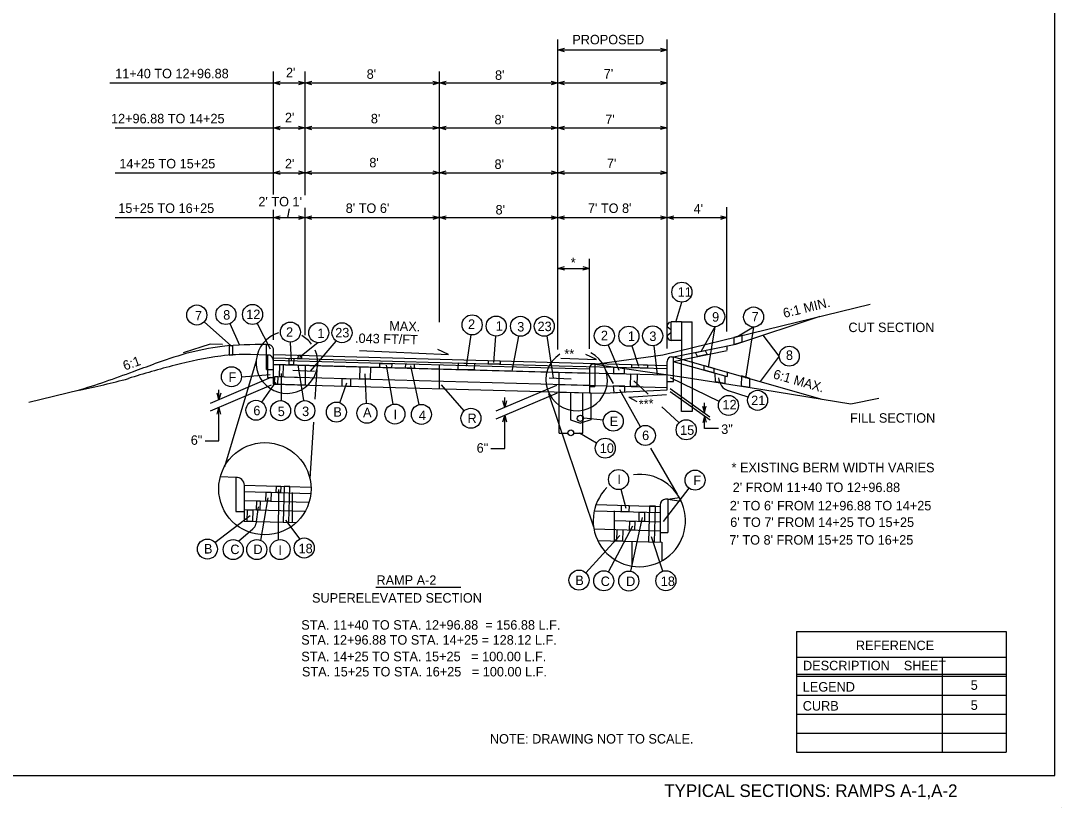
# Model space of a CAD drawing. Extents: x -210 to 558, y -150 to 205.
# Drawn here: x 491.9 to 557.8, y -150.3 to -100.6 of the extents above; entities that cross this region are included whole.
import ezdxf

# ---------------------------------------------------------------- set-up
doc = ezdxf.new("R2010")
doc.units = 0
for name, color, linetype in [('Level 1', 7, 'Continuous'), ('Level 4', 7, 'Continuous'), ('Level 6', 7, 'Continuous'), ('Level 60', 7, 'Continuous'), ('Level 7', 7, 'Continuous')]:
    doc.layers.add(name, color=color, linetype=linetype)

msp = doc.modelspace()

# ---------------------------------------------------------------- linework, layer by layer
at = {"layer": 'Level 1'}
for p, q in [((557.356, -148.31), (557.356, -64.342)), ((423.408, -148.31), (557.356, -148.31)), ((557.752, -150.31), (557.752, -150.31))]:
    msp.add_line(p, q, dxfattribs=at)
at = {"layer": 'Level 4'}
for p, q in [((525.911, -121.363), (525.911, -101.746)), ((532.821, -121.29), (532.821, -101.746)), ((525.911, -102.398), (532.821, -102.398)), ((507.923, -111.546), (507.923, -103.773)), ((509.923, -111.584), (509.923, -103.773)), ((518.423, -119.63), (518.423, -103.773)), ((497.577, -104.491), (507.923, -104.491)), ((507.923, -104.491), (509.923, -104.491)), ((509.923, -104.491), (518.423, -104.491)), ((518.276, -104.473), (518.693, -104.473)), ((518.423, -104.491), (525.911, -104.491)), ((525.911, -104.491), (532.821, -104.491)), ((497.908, -107.33), (507.923, -107.33)), ((507.923, -107.33), (509.923, -107.33)), ((509.923, -107.33), (518.423, -107.33)), ((518.276, -107.312), (518.693, -107.312)), ((518.423, -107.33), (525.911, -107.33)), ((525.911, -107.33), (532.821, -107.33)), ((497.908, -110.169), (507.923, -110.169)), ((507.923, -110.169), (509.923, -110.169)), ((509.923, -110.169), (518.423, -110.169)), ((518.276, -110.151), (518.693, -110.151)), ((518.423, -110.169), (525.911, -110.169)), ((525.911, -110.169), (532.821, -110.169)), ((507.923, -120.735), (507.923, -112.51)), ((508.912, -112.453), (508.798, -113.001)), ((509.923, -120.44), (509.923, -112.397)), ((536.611, -120.213), (536.611, -112.346)), ((497.908, -113.008), (507.923, -113.008)), ((507.923, -113.008), (509.923, -113.008)), ((509.923, -113.008), (518.423, -113.008)), ((518.276, -112.99), (518.693, -112.99)), ((518.423, -113.008), (525.911, -113.008)), ((525.911, -113.008), (536.611, -113.008)), ((527.911, -121.316), (527.911, -115.619)), ((525.911, -116.22), (527.911, -116.22)), ((533.38, -119.615), (533.756, -118.36)), ((503.543, -119.594), (505.267, -121.133)), ((505.167, -119.717), (505.768, -121.079)), ((506.884, -119.701), (507.71, -121.316)), ((520.398, -120.424), (520.111, -122.414)), ((535.832, -119.909), (534.965, -121.502)), ((535.832, -119.909), (535.428, -122.484)), ((538.293, -119.933), (537.346, -120.519)), ((538.293, -119.933), (537.789, -123.165)), ((539.917, -121.772), (538.906, -120.441)), ((503.923, -121.023), (502.211, -121.572)), ((504.706, -121.027), (503.923, -121.023)), ((508.985, -120.91), (509.046, -122.075)), ((510.718, -120.925), (509.59, -121.834)), ((510.265, -122.721), (511.894, -120.816)), ((521.966, -120.5), (521.848, -122.181)), ((523.429, -120.508), (522.995, -122.719)), ((525.222, -120.496), (525.607, -123.165)), ((529.096, -121.073), (529.761, -122.67)), ((513.359, -121.418), (518.984, -121.67)), ((518.984, -121.67), (518.319, -121.35)), ((528.349, -121.984), (527.684, -121.664)), ((530.596, -121.115), (531.011, -122.416)), ((531.981, -121.117), (532.192, -122.937)), ((509.84, -124.587), (509.486, -122.326)), ((515.498, -124.814), (515.074, -122.347)), ((517.144, -124.839), (516.614, -122.383)), ((526.09, -121.9), (528.349, -121.984)), ((539.917, -121.772), (538.7, -123.375)), ((505.898, -123.078), (507.719, -122.94)), ((508.43, -124.591), (508.424, -122.869)), ((513.803, -124.752), (513.713, -122.884)), ((507.747, -123.13), (503.911, -124.762)), ((507.778, -123.613), (503.911, -125.259)), ((507.194, -124.688), (508.062, -123.413)), ((512.114, -124.717), (512.567, -123.457)), ((519.993, -125.228), (518.548, -123.587)), ((525.829, -123.627), (521.993, -125.259)), ((530.717, -123.336), (531.631, -124.181)), ((536.114, -124.645), (533.037, -123.156)), ((504.465, -124.526), (504.465, -123.896)), ((525.861, -124.11), (521.993, -125.756)), ((531.136, -126.238), (529.837, -123.898)), ((530.398, -124.376), (532.792, -124.206)), ((530.398, -124.376), (530.912, -124.641)), ((533.012, -123.82), (535.534, -125.607)), ((533.013, -124.002), (535.543, -125.794)), ((537.944, -124.367), (536.703, -123.967)), ((504.465, -127.122), (504.465, -125.023)), ((522.547, -125.023), (522.547, -124.394)), ((532.497, -124.98), (533.573, -125.974)), ((535.178, -125.357), (535.178, -124.727)), ((522.547, -127.62), (522.547, -125.52)), ((528.799, -125.825), (527.544, -125.705)), ((535.188, -126.357), (535.188, -125.542)), ((536.064, -126.357), (535.188, -126.357)), ((528.361, -127.278), (527.28, -126.652)), ((503.589, -127.122), (504.465, -127.122)), ((521.671, -127.62), (522.547, -127.62)), ((508.243, -130.21), (508.214, -133.391)), ((529.904, -130.194), (530.209, -131.401)), ((534.201, -130.121), (532.568, -132.235)), ((507.123, -133.433), (507.595, -130.734)), ((506.956, -131.302), (506.814, -132.394)), ((504.22, -133.563), (506.45, -131.861)), ((508.687, -132.145), (509.587, -133.343)), ((530.534, -135.385), (531.266, -131.991)), ((505.714, -133.477), (506.618, -132.705)), ((529.111, -135.425), (530.656, -132.519)), ((527.676, -135.476), (529.822, -133.13)), ((532.546, -135.382), (531.836, -133.211)), ((514.403, -136.386), (519.778, -136.386)), ((541.015, -139.191), (541.015, -146.826)), ((541.015, -139.191), (554.27, -139.191)), ((554.27, -139.191), (554.27, -146.826)), ((541.015, -140.826), (554.27, -140.826)), ((550.224, -140.826), (550.224, -146.826)), ((541.015, -141.901), (554.27, -141.901)), ((541.015, -142.026), (554.27, -142.026)), ((541.015, -143.226), (554.27, -143.226)), ((541.015, -144.426), (554.27, -144.426)), ((541.015, -145.626), (554.27, -145.626)), ((541.015, -146.826), (554.27, -146.826))]:
    msp.add_line(p, q, dxfattribs=at)
for points in [[(526.331, -102.514), (525.911, -102.398), (526.331, -102.286)], [(532.401, -102.282), (532.821, -102.398), (532.401, -102.51)], [(508.343, -104.607), (507.923, -104.491), (508.343, -104.379)], [(509.503, -104.375), (509.923, -104.491), (509.503, -104.603)], [(510.343, -104.607), (509.923, -104.491), (510.343, -104.379)], [(518.003, -104.375), (518.423, -104.491), (518.003, -104.603)], [(518.843, -104.607), (518.423, -104.491), (518.843, -104.379)], [(525.491, -104.375), (525.911, -104.491), (525.491, -104.603)], [(526.331, -104.607), (525.911, -104.491), (526.331, -104.379)], [(532.401, -104.375), (532.821, -104.491), (532.401, -104.603)], [(508.343, -107.446), (507.923, -107.33), (508.343, -107.218)], [(509.503, -107.214), (509.923, -107.33), (509.503, -107.442)], [(510.343, -107.446), (509.923, -107.33), (510.343, -107.218)], [(518.003, -107.214), (518.423, -107.33), (518.003, -107.442)], [(518.843, -107.446), (518.423, -107.33), (518.843, -107.218)], [(525.491, -107.214), (525.911, -107.33), (525.491, -107.442)], [(526.331, -107.446), (525.911, -107.33), (526.331, -107.218)], [(532.401, -107.214), (532.821, -107.33), (532.401, -107.442)], [(508.343, -110.285), (507.923, -110.169), (508.343, -110.057)], [(509.503, -110.053), (509.923, -110.169), (509.503, -110.281)], [(510.343, -110.285), (509.923, -110.169), (510.343, -110.057)], [(518.003, -110.053), (518.423, -110.169), (518.003, -110.281)], [(518.843, -110.285), (518.423, -110.169), (518.843, -110.057)], [(525.491, -110.053), (525.911, -110.169), (525.491, -110.281)], [(526.331, -110.285), (525.911, -110.169), (526.331, -110.057)], [(532.401, -110.053), (532.821, -110.169), (532.401, -110.281)], [(508.343, -113.124), (507.923, -113.008), (508.343, -112.896)], [(509.503, -112.892), (509.923, -113.008), (509.503, -113.12)], [(510.343, -113.124), (509.923, -113.008), (510.343, -112.896)], [(518.003, -112.892), (518.423, -113.008), (518.003, -113.12)], [(518.843, -113.124), (518.423, -113.008), (518.843, -112.896)], [(525.491, -112.892), (525.911, -113.008), (525.491, -113.12)], [(526.331, -113.124), (525.911, -113.008), (526.331, -112.896)], [(532.401, -112.892), (532.821, -113.008), (532.401, -113.12)], [(533.241, -113.124), (532.821, -113.008), (533.241, -112.896)], [(536.191, -112.892), (536.611, -113.008), (536.191, -113.12)], [(526.331, -116.336), (525.911, -116.22), (526.331, -116.108)], [(527.491, -116.104), (527.911, -116.22), (527.491, -116.332)], [(504.581, -124.106), (504.465, -124.526), (504.353, -124.106)], [(504.349, -125.443), (504.465, -125.023), (504.577, -125.443)], [(522.663, -124.603), (522.547, -125.023), (522.435, -124.603)], [(535.062, -124.937), (535.178, -125.357), (535.29, -124.937)], [(522.431, -125.94), (522.547, -125.52), (522.659, -125.94)], [(535.304, -125.962), (535.188, -125.542), (535.076, -125.962)]]:
    msp.add_lwpolyline(points, dxfattribs=at)
for points in [[(537.035, -120.601), (537.049, -121.041), (537.577, -120.877), (537.573, -120.451)], [(534.624, -121.533), (535.236, -121.413), (535.366, -121.674), (534.753, -121.794)], [(535.17, -122.367), (535.771, -122.537), (535.768, -122.829), (535.167, -122.659)], [(535.871, -122.855), (536.464, -123.02), (536.474, -123.499), (535.879, -123.406)], [(537.518, -123.021), (537.516, -123.644), (538.055, -123.735), (538.052, -123.185)]]:
    msp.add_lwpolyline(points, close=True, dxfattribs=at)
for centre in [(533.757, -117.726), (503.07, -119.171), (504.911, -119.137), (506.595, -119.137), (535.834, -119.275), (538.295, -119.298), (508.99, -120.251), (510.785, -120.294), (512.255, -120.294), (520.489, -119.796), (522.011, -119.868), (523.551, -119.886), (525.05, -119.886), (528.852, -120.488), (530.404, -120.511), (531.908, -120.488), (540.551, -121.774), (505.264, -123.076), (536.702, -124.891), (538.545, -124.568), (506.815, -125.196), (508.369, -125.222), (509.905, -125.222), (511.899, -125.314), (513.833, -125.385), (515.606, -125.439), (517.278, -125.459), (520.412, -125.704), (529.419, -125.884), (531.444, -126.792), (534.029, -126.434), (528.91, -127.595), (529.749, -129.579), (534.589, -129.619), (503.741, -133.977), (505.375, -134.013), (506.866, -134.013), (508.34, -134.013), (509.866, -133.912), (527.248, -135.944), (528.813, -135.985), (530.4, -136.005), (532.743, -135.984)]:
    msp.add_circle(centre, 0.634, dxfattribs=at)
for centre, radius, start, end in [((537.033, -123.058), 0.967, 184.63452, 250.04639), ((506.33, -132.307), 0.491, 305.90709, 349.76504)]:
    msp.add_arc(centre, radius, start, end, dxfattribs=at)
at = {"layer": 'Level 6'}
for p, q in [((532.553, -121.696), (545.664, -118.477)), ((507.547, -121.702), (506.459, -121.669)), ((507.547, -121.702), (507.547, -123.134)), ((528.244, -122.283), (532.553, -121.696)), ((507.902, -122.021), (507.902, -123.548)), ((507.902, -122.036), (527.911, -122.586)), ((507.902, -122.3), (527.911, -122.85)), ((518.423, -123.838), (518.423, -122.325)), ((528.244, -122.283), (528.143, -122.283)), ((528.244, -122.283), (528.244, -123.692)), ((528.244, -122.283), (533.764, -123.072)), ((507.902, -123.062), (527.911, -123.613)), ((527.911, -122.532), (527.911, -124.099)), ((533.764, -123.072), (538.88, -123.878)), ((507.547, -123.134), (507.902, -123.134)), ((507.902, -123.548), (527.99, -124.101)), ((527.911, -123.692), (528.244, -123.692)), ((495.64, -123.927), (492.454, -124.7)), ((526.717, -124.066), (526.717, -125.796)), ((527.99, -124.101), (527.99, -125.796)), ((538.88, -123.878), (544.439, -124.792)), ((544.439, -124.792), (546.219, -124.423)), ((526.717, -125.8), (527.353, -126.01)), ((527.99, -125.8), (527.353, -126.01)), ((505.538, -129.443), (504.554, -129.414)), ((505.538, -129.443), (505.538, -131.592)), ((506.071, -129.922), (506.071, -132.213)), ((506.071, -129.945), (510.297, -130.061)), ((506.071, -130.341), (510.284, -130.457)), ((506.107, -130.907), (510.171, -131.019)), ((509.103, -130.396), (509.103, -132.297)), ((532.875, -130.824), (532.724, -130.824)), ((532.875, -130.824), (533.605, -130.724)), ((532.875, -130.824), (532.875, -132.939)), ((532.875, -130.824), (533.705, -130.942)), ((505.538, -131.592), (506.071, -131.592)), ((506.071, -131.485), (509.926, -131.591)), ((528.183, -131.56), (532.375, -131.676)), ((528.326, -131.168), (532.375, -131.279)), ((529.486, -133.468), (529.486, -131.567)), ((532.375, -131.198), (532.375, -133.548)), ((506.071, -132.213), (509.365, -132.304)), ((529.486, -132.182), (532.375, -132.262)), ((528.192, -132.704), (532.375, -132.819)), ((532.375, -132.939), (532.875, -132.939)), ((528.441, -133.44), (532.494, -133.551)), ((530.584, -133.499), (530.584, -135.053)), ((532.494, -133.551), (532.494, -134.719))]:
    msp.add_line(p, q, dxfattribs=at)
msp.add_circle((527.337, -125.709), 0.196, dxfattribs=at)
for centre, radius, start, end in [((506.143, -133.468), 11.803, 88.4676, 97.57992), ((507.569, -122.043), 0.342, 1.12623, 93.69626), ((514.292, -171.853), 51.086, 104.27965, 107.71771), ((507.498, -143.875), 22.298, 97.5041, 105.09419), ((528.153, -122.524), 0.242, 92.27579, 181.84757), ((482.471, -61.462), 63.839, 281.90418, 284.7694), ((505.571, -129.955), 0.513, 1.12623, 93.69626), ((532.738, -131.186), 0.363, 92.27579, 181.84757)]:
    msp.add_arc(centre, radius, start, end, dxfattribs=at)
at = {"layer": 'Level 60'}
for points in [[(505.347, -121.112), (505.112, -121.127), (505.112, -121.702), (505.354, -121.687)], [(509.492, -121.922), (509.498, -121.717), (509.694, -121.722), (509.688, -121.928)], [(508.301, -123.073), (508.322, -122.312), (508.533, -122.318), (508.512, -123.079)], [(508.907, -122.308), (508.918, -121.907), (509.207, -121.915), (509.196, -122.316)], [(514.645, -122.494), (514.652, -122.23), (515.398, -122.251), (515.391, -122.515)], [(516.276, -122.52), (516.292, -122.257), (516.829, -122.29), (516.813, -122.553)], [(519.609, -122.622), (519.62, -122.201), (520.631, -122.229), (520.62, -122.65)], [(521.526, -122.253), (521.532, -122.047), (522.262, -122.067), (522.256, -122.273)], [(530.589, -122.502), (530.595, -122.296), (531.586, -122.324), (531.58, -122.529)], [(507.993, -123.551), (508.007, -123.065), (508.188, -123.07), (508.175, -123.556)], [(513.374, -123.222), (513.395, -122.46), (514.055, -122.478), (514.034, -123.24)], [(529.444, -122.873), (529.455, -122.471), (530.115, -122.489), (530.103, -122.891)], [(530.496, -123.684), (530.517, -122.902), (530.926, -122.914), (530.904, -123.695)], [(512.263, -123.677), (512.276, -123.192), (512.803, -123.206), (512.789, -123.692)], [(529.444, -124.085), (530.149, -124.034), (530.15, -123.674), (529.42, -123.654)], [(508.097, -130.397), (508.107, -130.001), (508.381, -130.008), (508.37, -130.404)], [(508.594, -130.014), (508.532, -132.281), (508.887, -132.291), (508.949, -130.024)], [(506.853, -131.506), (506.869, -130.928), (507.076, -130.934), (507.06, -131.512)], [(507.44, -130.944), (507.455, -130.379), (507.778, -130.388), (507.763, -130.953)], [(506.257, -132.218), (506.278, -131.49), (506.624, -131.5), (506.604, -132.228)], [(529.933, -131.608), (529.944, -131.212), (530.422, -131.225), (530.411, -131.622)], [(531.701, -131.261), (531.638, -133.527), (532.032, -133.538), (532.094, -131.271)], [(530.439, -132.766), (530.455, -132.209), (530.774, -132.218), (530.759, -132.775)], [(531.046, -132.225), (531.062, -131.639), (531.398, -131.649), (531.382, -132.234)], [(529.639, -133.473), (529.659, -132.744), (530.02, -132.754), (530, -133.482)]]:
    msp.add_lwpolyline(points, close=True, dxfattribs=at)
at = {"layer": 'Level 7'}
for p, q in [((532.834, -119.829), (532.982, -119.625)), ((532.982, -119.625), (533.069, -119.61)), ((533.736, -119.61), (533.069, -119.61)), ((533.069, -120.776), (533.069, -119.61)), ((533.736, -119.61), (533.736, -121.86)), ((533.736, -119.61), (534.403, -119.61)), ((534.403, -122.112), (534.403, -119.61)), ((537.177, -121.011), (542.499, -119.254)), ((533.039, -120.084), (532.849, -119.937)), ((532.849, -120.449), (533.039, -120.301)), ((507.474, -122.609), (507.474, -121.04)), ((507.474, -121.04), (507.658, -121.04)), ((532.982, -120.761), (532.834, -120.556)), ((532.982, -120.761), (533.069, -120.776)), ((533.736, -120.776), (533.069, -120.776)), ((533.233, -121.812), (537.177, -121.011)), ((507.923, -123.549), (507.923, -121.441)), ((507.923, -121.673), (525.985, -122.17)), ((533.209, -122.103), (536.62, -121.41)), ((536.611, -121.126), (536.611, -121.372)), ((506.831, -122.06), (504.812, -128.771)), ((507.923, -121.879), (525.985, -122.376)), ((507.923, -122.281), (525.943, -122.777)), ((509.923, -122.336), (509.923, -123.604)), ((525.985, -122.17), (532.822, -122.358)), ((525.985, -122.376), (532.822, -122.564)), ((532.822, -123.895), (532.822, -122.105)), ((533.104, -121.812), (533.233, -121.812)), ((533.209, -122.103), (536.62, -123.064)), ((533.233, -123.371), (533.233, -121.812)), ((533.233, -121.812), (542.601, -124.49)), ((533.736, -125.276), (533.736, -121.86)), ((534.403, -122.112), (534.403, -125.276)), ((507.474, -122.609), (507.923, -122.609)), ((507.923, -123.063), (509.923, -123.118)), ((509.143, -122.669), (510.52, -122.733)), ((510.665, -122.645), (510.546, -124.505)), ((525.943, -122.777), (532.822, -122.966)), ((525.985, -124.046), (525.985, -122.778)), ((528.907, -122.64), (529.403, -123.496)), ((536.62, -122.772), (536.62, -123.064)), ((509.923, -123.604), (507.923, -123.549)), ((525.367, -123.154), (526.744, -123.218)), ((525.985, -123.56), (532.822, -123.748)), ((532.822, -123.371), (533.233, -123.371)), ((525.315, -124.13), (528.173, -132.581)), ((525.985, -124.046), (528.877, -124.125)), ((525.985, -126.652), (525.985, -124.046)), ((527.494, -126.652), (527.494, -124.089)), ((528.877, -124.125), (530.222, -124.029)), ((530.222, -124.029), (532.822, -123.895)), ((534.403, -125.276), (533.736, -125.276)), ((510.453, -125.957), (510.226, -129.514)), ((525.985, -126.652), (526.549, -126.652)), ((526.908, -126.652), (527.494, -126.652)), ((531.773, -127.59), (533.462, -130.506))]:
    msp.add_line(p, q, dxfattribs=at)
for centre, radius in [((526.729, -126.625), 0.18), ((507.378, -130.163), 2.92)]:
    msp.add_circle(centre, radius, dxfattribs=at)
for centre, radius, start, end in [((508.774, -122.182), 1.947, 105.71295, 23.99916), ((532.897, -119.875), 0.0781, 144.08393, 232.1285), ((532.991, -120.24), 0.0781, 307.8715, 360), ((507.205, -147.088), 26.049, 89.40827, 95.57705), ((507.566, -121.39), 0.361, 351.83326, 75.13882), ((508.774, -122.182), 1.947, 36.81944, 61.15971), ((532.897, -120.511), 0.0781, 127.8715, 215.91607), ((519.432, -178.387), 59.281, 106.72669, 108.74418), ((506.845, -138.351), 17.325, 97.20085, 104.96984), ((527.098, -123.284), 1.947, 123.2425, 62.52215), ((490.184, -96.619), 27.585, 288.76299, 291.69708), ((533.109, -122.1), 0.287, 91.07893, 181.04781), ((482.371, -79.561), 46.288, 286.48159, 291.12853), ((531.064, -132.173), 2.92, 134.46673, 97.29987)]:
    msp.add_arc(centre, radius, start, end, dxfattribs=at)

# ---------------------------------------------------------------- texts
at = {"layer": 'Level 1'}
msp.add_text('TYPICAL SECTIONS: RAMPS A-1,A-2', height=0.8, dxfattribs=at).set_placement((532.643, -149.665))
at = {"layer": 'Level 4'}
for s, p in [('PROPOSED', (526.825, -102.046)), ('11+40 TO 12+96.88', (497.908, -104.194)), ("2'", (508.713, -104.127)), ("8'", (513.817, -104.227)), ("8'", (521.937, -104.293)), ("7'", (528.814, -104.21)), ('12+96.88 TO 14+25', (497.643, -107.044)), ("2'", (508.647, -106.978)), ("8'", (514.082, -107.044)), ("8'", (521.904, -107.11)), ("7'", (528.914, -107.094)), ("8'", (513.985, -109.828)), ('14+25 TO 15+25', (498.171, -109.894)), ("2'", (508.647, -109.894)), ("8'", (521.904, -109.928)), ("7'", (529.013, -109.878)), ("2' TO 1'", (506.966, -112.298)), ('15+25 TO 16+25', (498.104, -112.712)), ("8' TO 6'", (512.491, -112.712)), ("8'", (521.97, -112.811)), ("7' TO 8'", (527.811, -112.714)), ("4'", (534.5, -112.75)), ('*', (526.724, -116.152)), ('11', (533.492, -118.014)), ('7', (502.953, -119.515)), ('8', (504.741, -119.463)), ('12', (506.2, -119.429)), ('9', (535.668, -119.591)), ('7', (538.172, -119.576)), ('2', (520.231, -120.048)), ('1', (521.983, -120.165)), ('3', (523.342, -120.213)), ('23', (524.628, -120.191)), ('CUT SECTION', (544.292, -120.252)), ('2', (508.716, -120.549)), ('1', (510.7, -120.631)), ('23', (511.829, -120.586)), ('2', (528.635, -120.765)), ('1', (530.34, -120.813)), ('3', (531.7, -120.815)), ('**', (526.32, -121.928)), ('8', (540.339, -122.014)), ('F', (505.078, -123.4)), ('21', (538.14, -124.875)), ('6', (506.647, -125.513)), ('5', (508.19, -125.567)), ('3', (509.732, -125.567)), ('B', (511.708, -125.602)), ('A', (513.588, -125.637)), ('12', (536.326, -125.141)), ('I', (515.522, -125.763)), ('4', (517.116, -125.816)), ('R', (520.196, -126.004)), ('E', (529.194, -126.203)), ('FILL SECTION', (544.391, -125.985)), ('15', (533.645, -126.752)), ('3"', (536.245, -126.695)), ('6"', (502.69, -127.383)), ('6', (531.242, -127.085)), ('6"', (520.773, -127.88)), ('10', (528.563, -127.896)), ('* EXISTING BERM WIDTH VARIES', (536.899, -129.118)), ('I', (529.68, -129.871)), ('F', (534.479, -129.932)), ("2' FROM 11+40 TO 12+96.88", (536.973, -130.373)), ("2' TO 6' FROM 12+96.88 TO 14+25", (536.789, -131.532)), ("6' TO 7' FROM 14+25 TO 15+25", (536.813, -132.579)), ("7' TO 8' FROM 15+25 TO 16+25", (536.764, -133.699)), ('B', (503.524, -134.261)), ('C', (505.193, -134.297)), ('D', (506.649, -134.297)), ('I', (508.23, -134.35)), ('18', (509.509, -134.244)), ('RAMP A-2', (514.436, -136.242)), ('B', (527.016, -136.256)), ('C', (528.623, -136.317)), ('D', (530.229, -136.317)), ('18', (532.425, -136.317)), ('SUPERELEVATED SECTION', (510.361, -137.369)), ('STA. 11+40 TO STA. 12+96.88  = 156.88 L.F.', (509.679, -139.079)), ('STA. 12+96.88 TO STA. 14+25 = 128.12 L.F.', (509.675, -140.026)), ('REFERENCE', (544.764, -140.373)), ('STA. 14+25 TO STA. 15+25   = 100.00 L.F.', (509.681, -141.075)), ('STA. 15+25 TO STA. 16+25   = 100.00 L.F.', (509.722, -142.037)), ('DESCRIPTION    SHEET', (541.422, -141.647)), ('LEGEND', (541.405, -142.996)), ('5', (552.029, -142.887)), ('CURB', (541.405, -144.196)), ('5', (552.029, -144.157)), ('NOTE: DRAWING NOT TO SCALE.', (521.611, -146.285))]:
    msp.add_text(s, height=0.6, dxfattribs=at).set_placement(p)
for s, rotation, p in [('6:1 MIN.', 13.79506, (540.235, -119.36)), ('MAX.', 358.42591, (515.238, -120.156)), ('.043 FT/FT', 358.42591, (513.075, -120.928)), ('6:1', 19.53014, (498.523, -122.688)), ('6:1 MAX.', 344.04801, (539.487, -123.171)), ('***', 4.07739, (531.058, -125.127))]:
    msp.add_text(s, height=0.6, rotation=rotation, dxfattribs=at).set_placement(p)

doc.saveas('drawing.dxf')
